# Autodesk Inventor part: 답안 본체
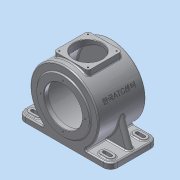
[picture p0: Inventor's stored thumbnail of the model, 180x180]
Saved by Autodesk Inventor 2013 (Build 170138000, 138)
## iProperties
Created: 2015-06
Part Number: 답안 본체
Material: 알루미늄 6061
Document SubType Name: Modeling
Designer: Administrator
Density: 2.71 g/cm^3
Mass: 3274.95 g
Surface Area: 2300.5 cm^2
Volume: 1208.47 cm^3
Author: Administrator
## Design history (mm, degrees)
sketch "스케치1"
  geometry: C1 r 85 at (0, 0); 1 further point
  constraints: 1 centre point, 1 coincident
  dimensions: "d0" = 170 diameter of C1
extrude "돌출1" new body sketch "스케치1" stored distance "d2" = 118; taper "d3" = 0 deg
sketch "스케치2"
  geometry: L1 (0, 0)-(0, -85); L2 (-115, -85)-(115, -85); L3 (115, -85)-(115, -71); L4 (115, -71)-(-115, -71); L5 (-115, -71)-(-115, -85)
  constraints: 10 end point, 3 perpendicular, 1 midpoint, 1 parallel, 1 vertical
  dimensions: "d4" = 85 distance of L1.end L1.start; "d5" = 230 distance of L2.start L2.end; "d6" = 14 distance of L2.end L3.end
extrude "돌출2" join sketch "스케치2" stored distance "d7" = 118; taper "d8" = 0 deg
sketch "스케치3"
  geometry: C1 r 65 at (0, 0); A1 r 85 centre (0, 0) between (46.733, -71) and (-46.733, -71) reference
  constraints: 1 centre point, 1 coincident
  dimensions: "d9" = 130 diameter of C1
extrude "돌출3" join sketch "스케치3" distance "d10" = 13; taper "d11" = 0 deg
sketch "스케치4"
  geometry: C1 r 65 at (0, 0); A1 r 85 centre (0, 0) between (46.733, -71) and (-46.733, -71) reference
  constraints: 1 centre point, 1 coincident
  dimensions: "d12" = 130 diameter of C1
extrude "돌출4" join sketch "스케치4" distance "d14" = 3; taper "d15" = 0 deg
sketch "스케치5"
  geometry: C1 r 65 at (0, 0) reference; C2 r 47.5 at (0, 0)
  constraints: 1 centre point, 1 coincident
  dimensions: "d16" = 95 diameter of C2
extrude "돌출5" cut sketch "스케치5" distance "d17" = 11; taper "d18" = 0 deg
sketch "스케치6"
  geometry: C1 r 47.5 at (0, 0) reference; C2 r 77 at (0, 0)
  constraints: 1 centre point, 1 coincident
  dimensions: "d19" = 154 diameter of C2
extrude "돌출6" cut sketch "스케치6" distance "d21" = 102; taper "d22" = 0 deg
sketch "스케치7"
  geometry: C1 r 77 at (0, 0) reference; C2 r 31 at (0, 0)
  constraints: 1 centre point, 1 coincident
  dimensions: "d23" = 62 diameter of C2
extrude "돌출7" join sketch "스케치7" distance "d24" = 3.5; taper "d25" = -25 deg
sketch "스케치8"
  geometry: C1 r 29.368 at (0, 0) reference; C2 r 23.5 at (0, 0)
  constraints: 1 centre point, 1 coincident
  dimensions: "d26" = 47 diameter of C2
extrude "돌출8" cut sketch "스케치8" distance "d27" = 14; taper "d28" = 0 deg
sketch "스케치9"
  geometry: C1 r 23.5 at (0, 0) reference; C2 r 15 at (0, 0)
  constraints: 1 centre point, 1 coincident
  dimensions: "d29" = 30 diameter of C2
extrude "돌출9" cut sketch "스케치9" distance "d31" = 3; taper "d32" = 0 deg
sketch "스케치10"
  geometry: L1 (-109, -71)-(-84.87, -4.703); L2 (-115, -85)-(-115, -71) reference; L3 (-115, -71)-(-46.733, -71) reference; A1 r 85 centre (0, 0) between (46.733, -71) and (-46.733, -71) reference; 1 further point
  constraints: 2 end point, 1 point on circle, 1 point on line
  dimensions: "d33" = 6 distance from line of L2 L1.start; "d34" = 110 deg angle of L3 L1
feature "리브1" sketch "스케치10" dims "d35" = 1, "d36" = 15, "d37" = 0, "d38" = 0, "d39" = 1, "d40" = 1
sketch "스케치11"
  geometry: L1 (0, 118)-(68.267, 118) reference; L2 (-16.934, 8)-(-16.934, 110) reference; L3 (-16.934, 110)-(-76.533, 110) reference; L4 (-76.533, 110)-(-76.533, 8) reference; L5 (-76.533, 8)-(-16.934, 8) reference; L6 (68.267, 118)-(68.267, 0) reference; L7 (68.267, 0)-(0, 0) reference; L8 (0, 51.5)-(0, 0) reference; L9 (62.267, 51.5)-(0, 51.5) reference; L10 (62.267, 66.5)-(62.267, 51.5) reference; L11 (0, 66.5)-(62.267, 66.5) reference; L12 (0, 118)-(0, 66.5) reference; L13 (-93.467, 118)-(0, 118) reference; L14 (-93.467, 66.5)-(-93.467, 118) reference; L15 (-155.733, 66.5)-(-93.467, 66.5) reference; L16 (-155.733, 51.5)-(-155.733, 66.5) reference; L17 (-93.467, 51.5)-(-155.733, 51.5) reference; L18 (-93.467, 0)-(-93.467, 51.5) reference; L19 (-93.467, 0)-(-161.733, 0) reference; L20 (-161.733, 0)-(-161.733, 118) reference; L21 (-161.733, 118)-(-93.467, 118) reference; L22 (0, 118)-(68.267, 118) reference; L23 (0, 0)-(-93.467, 0) reference; L24 (-143.733, 100)-(50.267, 100); L25 (50.267, 100)-(50.267, 18); L26 (50.267, 18)-(-143.733, 18); L27 (-143.733, 18)-(-143.733, 100); L28 (50.267, 100)-(-143.733, 18); L29 (50.267, 18)-(-143.733, 100); L30 (34.267, 91)-(50.267, 91); L31 (34.267, 109)-(50.267, 109); A1 r 9 centre (50.267, 100) between (50.267, 91) and (50.267, 109); A2 r 9 centre (34.267, 100) between (34.267, 91) and (34.267, 109); 2 further points
  constraints: 16 end point, 4 point on circle, 3 parallel, 2 centre point, 2 coincident, 2 point on line, 2 tangent, 1 horizontal, 1 midpoint, 1 perpendicular
  dimensions: "d41" = 18 distance between parallel lines of L1 L24; "d42" = 194 distance of L24.start L24.end; "d43" = 18 diameter of A1; "d44" = 18 diameter of A2; "d45" = 16 distance of A2.centre L24.end
extrude "돌출10" join sketch "스케치11" distance "d46" = 3; taper "d47" = 0 deg
sketch "스케치12"
  geometry: L1 (34.267, 91)-(50.267, 91) reference; L2 (34.267, 96)-(50.267, 96); L3 (34.267, 104)-(50.267, 104); A1 r 9 centre (50.267, 100) between (50.267, 91) and (50.267, 109) reference; A2 r 9 centre (34.267, 100) between (34.267, 109) and (34.267, 91) reference; A3 r 4 centre (34.267, 100) between (34.267, 96) and (34.267, 104); A4 r 4 centre (50.267, 100) between (50.267, 96) and (50.267, 104); 1 further point
  constraints: 4 end point, 4 point on circle, 2 centre point, 2 coincident, 2 parallel, 2 tangent
  dimensions: "d48" = 8 diameter of A3; "d49" = 8 diameter of A4
extrude "돌출11" cut sketch "스케치12" stored distance "d50" = 3; taper "d51" = 0 deg
sketch "스케치13"
  geometry: L1 (212, 104)-(196, 104) reference; L2 (196, 96)-(212, 96) reference; L3 (212, 91)-(196, 91) reference; L4 (196, 109)-(212, 109) reference; L5 (144.799, 8)-(144.799, 110) reference; L6 (144.799, 110)-(85.201, 110) reference; L7 (85.201, 110)-(85.201, 8) reference; L8 (85.201, 8)-(144.799, 8) reference; L9 (230, 118)-(230, 0) reference; L10 (230, 0)-(161.733, 0) reference; L11 (161.733, 51.5)-(161.733, 0) reference; L12 (224, 51.5)-(161.733, 51.5) reference; L13 (224, 66.5)-(224, 51.5) reference; L14 (161.733, 66.5)-(224, 66.5) reference; L15 (161.733, 118)-(161.733, 66.5) reference; L16 (68.267, 118)-(161.733, 118) reference; L17 (68.267, 66.5)-(68.267, 118) reference; L18 (6, 66.5)-(68.267, 66.5) reference; L19 (6, 51.5)-(6, 66.5) reference; L20 (68.267, 51.5)-(6, 51.5) reference; L21 (68.267, 0)-(68.267, 51.5) reference; L22 (68.267, 0)-(0, 0) reference; L23 (0, 0)-(0, 118) reference; L24 (0, 118)-(68.267, 118) reference; L25 (161.733, 118)-(230, 118) reference; L26 (161.733, 0)-(68.267, 0) reference; L27 (18, 100)-(212, 100) reference; L28 (212, 18)-(18, 100) reference; L29 (18, 18)-(18, 100) reference; L30 (212, 18)-(18, 18) reference; L31 (212, 100)-(212, 18) reference; L32 (18, 9)-(34, 9); L33 (18, 27)-(34, 27); L34 (18, 91)-(34, 91); L35 (34, 109)-(18, 109); L36 (212, 27)-(196, 27); L37 (212, 9)-(196, 9); A1 r 4 centre (196, 100) between (196, 104) and (196, 96) reference; A2 r 4 centre (212, 100) between (212, 96) and (212, 104) reference; A3 r 9 centre (196, 100) between (196, 109) and (196, 91) reference; A4 r 9 centre (212, 100) between (212, 91) and (212, 109) reference; A5 r 9 centre (212, 18) between (212, 27) and (212, 9); A6 r 9 centre (196, 18) between (196, 27) and (196, 9); A7 r 9 centre (18, 18) between (18, 9) and (18, 27); A8 r 9 centre (18, 100) between (18, 91) and (18, 109); A9 r 9 centre (34, 100) between (34, 91) and (34, 109); A10 r 9 centre (34, 18) between (34, 9) and (34, 27); 1 further point
  constraints: 12 end point, 12 point on circle, 7 tangent, 6 centre point, 5 point on line, 3 coincident, 2 parallel, 2 perpendicular, 1 vertical alignment
  dimensions: "d52" = 18 diameter of A5; "d53" = 18 diameter of A6; "d54" = 18 diameter of A7; "d55" = 18 diameter of A8; "d56" = 18 diameter of A9; "d57" = 18 diameter of A10; "d58" = 16 distance of A10.centre A7.centre; "d59" = 16 distance of A9.centre L27.start
extrude "돌출12" join sketch "스케치13" distance "d60" = 3; taper "d61" = 0 deg
sketch "스케치14"
  geometry: L1 (50.267, 9)-(34.267, 9) reference; L2 (34.267, 27)-(50.267, 27) reference; L3 (-143.733, 27)-(-127.733, 27) reference; L4 (-127.733, 9)-(-143.733, 9) reference; L5 (-143.733, 109)-(-127.733, 109) reference; L6 (-127.733, 91)-(-143.733, 91) reference; L7 (50.267, 104)-(34.267, 104) reference; L8 (34.267, 96)-(50.267, 96) reference; L9 (50.267, 91)-(34.267, 91) reference; L10 (34.267, 109)-(50.267, 109) reference; L11 (-16.934, 8)-(-16.934, 110) reference; L12 (-16.934, 110)-(-76.533, 110) reference; L13 (-76.533, 110)-(-76.533, 8) reference; L14 (-76.533, 8)-(-16.934, 8) reference; L15 (68.267, 118)-(68.267, 0) reference; L16 (68.267, 0)-(0, 0) reference; L17 (0, 51.5)-(0, 0) reference; L18 (62.267, 51.5)-(0, 51.5) reference; L19 (62.267, 66.5)-(62.267, 51.5) reference; L20 (0, 66.5)-(62.267, 66.5) reference; L21 (0, 118)-(0, 66.5) reference; L22 (-93.467, 118)-(0, 118) reference; L23 (-93.467, 66.5)-(-93.467, 118) reference; L24 (-155.733, 66.5)-(-93.467, 66.5) reference; L25 (-155.733, 51.5)-(-155.733, 66.5) reference; L26 (-93.467, 51.5)-(-155.733, 51.5) reference; L27 (-93.467, 0)-(-93.467, 51.5) reference; L28 (-93.467, 0)-(-161.733, 0) reference; L29 (-161.733, 0)-(-161.733, 118) reference; L30 (-161.733, 118)-(-93.467, 118) reference; L31 (0, 118)-(68.267, 118) reference; L32 (0, 0)-(-93.467, 0) reference; L33 (-143.733, 96)-(-127.733, 96); L34 (-127.733, 104)-(-143.733, 104); L35 (-143.733, 22)-(-127.733, 22); L36 (-127.733, 14)-(-143.733, 14); L37 (34.267, 14)-(50.267, 14); L38 (34.267, 22)-(50.267, 22); A1 r 9 centre (34.267, 18) between (34.267, 27) and (34.267, 9) reference; A2 r 9 centre (50.267, 18) between (50.267, 9) and (50.267, 27) reference; A3 r 9 centre (-127.733, 18) between (-135.733, 22.123) and (-135.733, 13.877) reference; A4 r 9 centre (-143.733, 18) between (-135.733, 13.877) and (-135.733, 22.123) reference; A5 r 9 centre (-143.733, 18) between (-143.733, 27) and (-143.733, 9) reference; A6 r 9 centre (-127.733, 18) between (-127.733, 9) and (-127.733, 27) reference; A7 r 9 centre (-143.733, 100) between (-143.733, 109) and (-143.733, 91) reference; A8 r 9 centre (-127.733, 100) between (-127.733, 91) and (-127.733, 109) reference; A9 r 4 centre (34.267, 100) between (34.267, 104) and (34.267, 96) reference; A10 r 4 centre (50.267, 100) between (50.267, 96) and (50.267, 104) reference; A11 r 9 centre (34.267, 100) between (34.267, 109) and (34.267, 91) reference; A12 r 9 centre (50.267, 100) between (50.267, 91) and (50.267, 109) reference; A13 r 4 centre (50.267, 18) between (50.267, 14) and (50.267, 22); A14 r 4 centre (34.267, 18) between (34.267, 14) and (34.267, 22); A15 r 4 centre (-127.733, 18) between (-127.733, 22) and (-127.733, 14); A16 r 4 centre (-143.733, 18) between (-143.733, 22) and (-143.733, 14); A17 r 4 centre (-127.733, 100) between (-127.733, 96) and (-127.733, 104); A18 r 4 centre (-143.733, 100) between (-143.733, 96) and (-143.733, 104); 1 further point
  constraints: 12 end point, 12 point on circle, 8 tangent, 6 centre point, 6 coincident, 4 parallel
  dimensions: "d62" = 8 diameter of A13; "d63" = 8 diameter of A14; "d64" = 8 diameter of A15; "d65" = 8 diameter of A16; "d66" = 8 diameter of A17; "d67" = 8 diameter of A18
extrude "돌출13" cut sketch "스케치14" distance "d68" = 3; taper "d69" = 0 deg; dims "d70" = 14, "d71" = 0
fillet "모깎기11" dims "d120" = 3
fillet "모깎기1" dims "d72" = 18
fillet "모깎기2" dims "d73" = 7.5
fillet "모깎기3" dims "d74" = 3
chamfer "모따기1" distance "d75" = 1; stored, may be unused: second distance "d76" = 2, angle "d77" = 45 deg
sketch "스케치15"
  geometry: C1 r 65 at (0, 0) reference; 1 further point
  constraints: 1 vertical alignment
  dimensions: "d78" = 55 distance of C1.centre point (0, 55)
hole "구멍1" sketch "스케치15" at (0, 55) diameter "d79" = 3.459; stored, may be unused: countersink angle "d83" = 90 deg, drill point angle "d85" = 118 deg; dims "d80" = 11, "d81" = 4, "d82" = 2, "d84" = 11
node "작업 평면1"
sketch "스케치16"
  geometry: L1 (-139.5, 16.5)-(-54.5, 16.5); L2 (-54.5, 16.5)-(-54.5, 101.5); L3 (-54.5, 101.5)-(-139.5, 101.5); L4 (-139.5, 101.5)-(-139.5, 16.5); L5 (-139.5, 16.5)-(-54.5, 101.5); L6 (-54.5, 16.5)-(-139.5, 101.5); 1 further point
  constraints: 12 end point, 2 midpoint, 2 parallel, 1 horizontal, 1 perpendicular
  dimensions: "d90" = 85 distance of L3.end L2.end; "d91" = 85 distance of L2.end L1.end
extrude "돌출14" join sketch "스케치16" stored distance "d92" = 3; taper "d93" = 0 deg
sketch "스케치17"
  geometry: C1 r 35 at (97, -59); 1 further point
  constraints: 1 centre point, 1 coincident
  dimensions: "d94" = 70 diameter of C1
extrude "돌출15" cut sketch "스케치17" stored distance "d95" = 3; taper "d96" = 0 deg
fillet "모깎기4" dims "d97" = 7
fillet "모깎기5" dims "d98" = 3
fillet "모깎기6" dims "d99" = 3
node "작업 평면5"
  node "작업 평면4"
sketch "스케치18"
  geometry: 2 further points
  constraints: 1 coincident, 1 other
feature "엠보싱1" sketch "스케치18" dims "d0" = 170, "d102" = 0.5, "d103" = 0
chamfer "모따기2" distance "d104" = 1; stored, may be unused: second distance "d105" = 2, angle "d106" = 45 deg
sketch "스케치19"
  geometry: L1 (61.5, -94.5)-(132.5, -94.5); L2 (132.5, -94.5)-(132.5, -23.5); L3 (132.5, -23.5)-(61.5, -23.5); L4 (61.5, -23.5)-(61.5, -94.5); L5 (61.5, -94.5)-(132.5, -23.5); L6 (132.5, -94.5)-(61.5, -23.5); C1 r 36 at (97, -59) reference; A1 r 7 centre (132.5, -23.5) between (139.5, -23.5) and (132.5, -16.5) reference; 4 further points
  constraints: 12 end point, 4 coincident, 2 midpoint, 2 parallel, 1 horizontal, 1 perpendicular
  dimensions: "d107" = 71 distance of L3.end L2.end (derived); "d108" = 71 distance of L2.end L1.end (derived)
hole "구멍2" sketch "스케치19" at (61.5, -23.5), (61.5, -94.5), (132.5, -94.5), (132.5, -23.5) diameter "d109" = 3.459; stored, may be unused: countersink angle "d113" = 90 deg, drill point angle "d115" = 118 deg; dims "d110" = 10, "d111" = 4, "d112" = 2, "d114" = 13
fillet "모깎기7" dims "d116" = 3
fillet "모깎기8" dims "d117" = 3
fillet "모깎기9" dims "d118" = 0.3
fillet "모깎기10" dims "d119" = 3
node "솔리드1"
mirror "대칭1"
pattern_circular "원형 패턴1" dims angle "d87" = 360 deg
node "절단 모서리 투영1"
node "절단 모서리 투영2"
node "절단 모서리 투영3"
other parameters: "d89" = -173, "d101" = -65 deg
